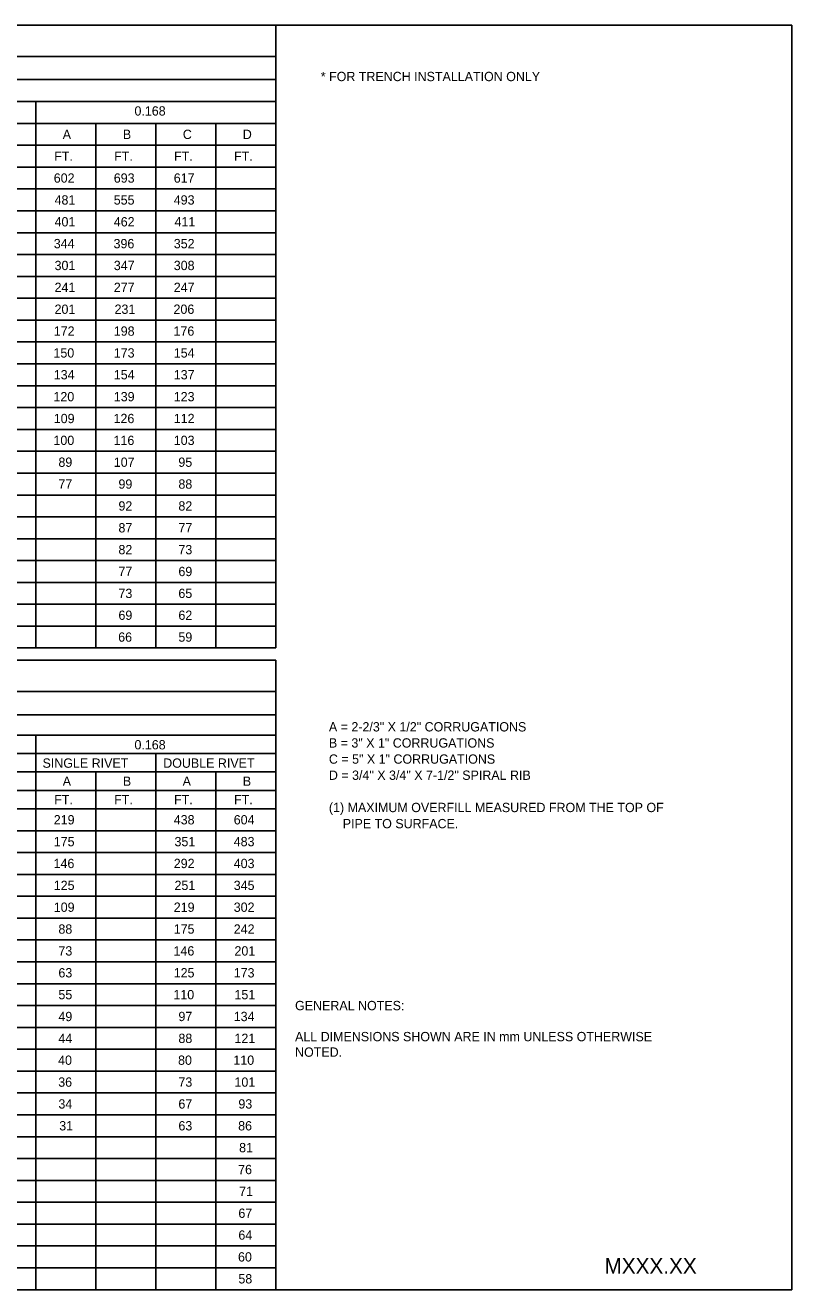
# Model space of a CAD drawing. Extents: x -439.1 to -407.9, y -458.1 to -436.2.
# Drawn here: x -420.2 to -407.86, y -458.05 to -437.68 of the extents above; entities that cross this region are included whole.
import ezdxf

# ---------------------------------------------------------------- set-up
doc = ezdxf.new("R2010")
doc.units = 0
for name, color, linetype in [('Draft_Named_Boundary', 7, 'Continuous'), ('Level 4', 7, 'Continuous'), ('Level 45', 7, 'Continuous'), ('Level 46', 7, 'Continuous')]:
    doc.layers.add(name, color=color, linetype=linetype)

msp = doc.modelspace()

# ---------------------------------------------------------------- linework, layer by layer
at = {"layer": 'Draft_Named_Boundary'}
msp.add_lwpolyline([(-439.109, -458.051), (-407.859, -458.051), (-407.859, -437.676), (-439.109, -437.676)], close=True, dxfattribs=at)
at = {"layer": 'Level 4'}
for p, q in [((-439.109, -437.676), (-416.17, -437.676)), ((-416.17, -447.71), (-416.17, -437.676)), ((-439.109, -438.177), (-416.17, -438.177)), ((-439.109, -438.552), (-416.17, -438.552)), ((-435.493, -438.905), (-416.17, -438.905)), ((-420.035, -447.71), (-420.035, -438.905)), ((-435.493, -439.257), (-416.17, -439.257)), ((-419.069, -447.71), (-419.069, -439.257)), ((-418.103, -447.71), (-418.103, -439.257)), ((-417.136, -447.71), (-417.136, -439.257)), ((-439.109, -439.609), (-416.17, -439.609)), ((-439.109, -439.961), (-416.17, -439.961)), ((-439.109, -440.313), (-416.17, -440.313)), ((-439.109, -440.666), (-416.17, -440.666)), ((-439.109, -441.018), (-416.17, -441.018)), ((-439.109, -441.37), (-416.17, -441.37)), ((-439.109, -441.722), (-416.17, -441.722)), ((-439.109, -442.075), (-416.17, -442.075)), ((-439.109, -442.427), (-416.17, -442.427)), ((-439.109, -442.779), (-416.17, -442.779)), ((-439.109, -443.131), (-416.17, -443.131)), ((-439.109, -443.483), (-416.17, -443.483)), ((-439.109, -443.836), (-416.17, -443.836)), ((-439.109, -444.188), (-416.17, -444.188)), ((-439.109, -444.54), (-416.17, -444.54)), ((-439.109, -444.892), (-416.17, -444.892)), ((-439.109, -445.245), (-416.17, -445.245)), ((-439.109, -445.597), (-416.17, -445.597)), ((-439.109, -445.949), (-416.17, -445.949)), ((-439.109, -446.301), (-416.17, -446.301)), ((-439.109, -446.654), (-416.17, -446.654)), ((-439.109, -447.006), (-416.17, -447.006)), ((-439.109, -447.358), (-416.17, -447.358)), ((-439.109, -447.71), (-416.17, -447.71)), ((-439.109, -447.908), (-416.17, -447.908)), ((-416.17, -458.051), (-416.17, -447.908)), ((-439.109, -448.409), (-416.17, -448.409)), ((-439.109, -448.785), (-416.17, -448.785)), ((-435.493, -449.113), (-416.17, -449.113)), ((-420.035, -458.051), (-420.035, -449.113)), ((-435.493, -449.411), (-416.17, -449.411)), ((-418.103, -458.051), (-418.103, -449.411)), ((-435.493, -449.708), (-416.17, -449.708)), ((-419.069, -458.051), (-419.069, -449.708)), ((-417.136, -458.051), (-417.136, -449.708)), ((-439.109, -450.005), (-416.17, -450.005)), ((-439.109, -450.302), (-416.17, -450.302)), ((-439.109, -450.654), (-416.17, -450.654)), ((-439.109, -451.006), (-416.17, -451.006)), ((-439.109, -451.359), (-416.17, -451.359)), ((-439.109, -451.711), (-416.17, -451.711)), ((-439.109, -452.063), (-416.17, -452.063)), ((-439.109, -452.415), (-416.17, -452.415)), ((-439.109, -452.767), (-416.17, -452.767)), ((-439.109, -453.12), (-416.17, -453.12)), ((-439.109, -453.472), (-416.17, -453.472)), ((-439.109, -453.824), (-416.17, -453.824)), ((-439.109, -454.176), (-416.17, -454.176)), ((-439.109, -454.529), (-416.17, -454.529)), ((-439.109, -454.881), (-416.17, -454.881)), ((-439.109, -455.233), (-416.17, -455.233)), ((-439.109, -455.585), (-416.17, -455.585)), ((-439.109, -455.937), (-416.17, -455.937)), ((-439.109, -456.29), (-416.17, -456.29)), ((-439.109, -456.642), (-416.17, -456.642)), ((-439.109, -456.994), (-416.17, -456.994)), ((-439.109, -457.346), (-416.17, -457.346)), ((-439.109, -457.699), (-416.17, -457.699)), ((-439.109, -458.051), (-416.17, -458.051))]:
    msp.add_line(p, q, dxfattribs=at)

# ---------------------------------------------------------------- texts
for s, p in [('* FOR TRENCH INSTALLATION ONLY', (-415.445, -438.576)), ('0.168', (-418.446, -439.131)), ('A', (-419.602, -439.508)), ('B', (-418.633, -439.508)), ('C', (-417.667, -439.508)), ('D', (-416.701, -439.508)), ('FT.', (-419.739, -439.86)), ('FT.', (-418.773, -439.86)), ('FT.', (-417.807, -439.86)), ('FT.', (-416.841, -439.86)), ('602', (-419.746, -440.212)), ('693', (-418.779, -440.212)), ('617', (-417.813, -440.212)), ('481', (-419.733, -440.565)), ('555', (-418.78, -440.565)), ('493', (-417.813, -440.565)), ('401', (-419.733, -440.917)), ('462', (-418.779, -440.917)), ('411', (-417.801, -440.917)), ('344', (-419.746, -441.269)), ('396', (-418.783, -441.269)), ('352', (-417.813, -441.269)), ('301', (-419.733, -441.621)), ('347', (-418.779, -441.621)), ('308', (-417.813, -441.621)), ('241', (-419.733, -441.973)), ('277', (-418.779, -441.973)), ('247', (-417.813, -441.973)), ('201', (-419.733, -442.326)), ('231', (-418.767, -442.326)), ('206', (-417.817, -442.326)), ('172', (-419.746, -442.678)), ('198', (-418.779, -442.678)), ('176', (-417.817, -442.678)), ('150', (-419.751, -443.03)), ('173', (-418.779, -443.03)), ('154', (-417.813, -443.03)), ('134', (-419.746, -443.382)), ('154', (-418.779, -443.382)), ('137', (-417.813, -443.382)), ('120', (-419.751, -443.735)), ('139', (-418.779, -443.735)), ('123', (-417.813, -443.735)), ('109', (-419.746, -444.087)), ('126', (-418.783, -444.087)), ('112', (-417.813, -444.087)), ('100', (-419.751, -444.439)), ('116', (-418.783, -444.439)), ('103', (-417.813, -444.439)), ('89', (-419.671, -444.791)), ('107', (-418.779, -444.791)), ('95', (-417.739, -444.791)), ('77', (-419.671, -445.143)), ('99', (-418.704, -445.143)), ('88', (-417.738, -445.143)), ('92', (-418.704, -445.496)), ('82', (-417.738, -445.496)), ('87', (-418.704, -445.848)), ('77', (-417.738, -445.848)), ('82', (-418.704, -446.2)), ('73', (-417.738, -446.2)), ('77', (-418.704, -446.552)), ('69', (-417.738, -446.552)), ('73', (-418.704, -446.905)), ('65', (-417.739, -446.905)), ('69', (-418.704, -447.257)), ('62', (-417.738, -447.257)), ('66', (-418.708, -447.609)), ('59', (-417.738, -447.609)), ('0.168', (-418.446, -449.344)), ('SINGLE RIVET', (-419.927, -449.64)), ('DOUBLE RIVET', (-417.983, -449.64)), ('A', (-419.602, -449.931)), ('B', (-418.633, -449.931)), ('A', (-417.67, -449.931)), ('B', (-416.701, -449.931)), ('FT.', (-419.739, -450.228)), ('FT.', (-418.773, -450.228)), ('FT.', (-417.807, -450.228)), ('FT.', (-416.841, -450.228)), ('219', (-419.746, -450.553)), ('438', (-417.813, -450.553)), ('604', (-416.847, -450.553)), ('175', (-419.746, -450.905)), ('351', (-417.801, -450.905)), ('483', (-416.847, -450.905)), ('146', (-419.749, -451.257)), ('292', (-417.813, -451.257)), ('403', (-416.847, -451.257)), ('125', (-419.746, -451.61)), ('251', (-417.801, -451.61)), ('345', (-416.847, -451.61)), ('109', (-419.746, -451.962)), ('219', (-417.813, -451.962)), ('302', (-416.847, -451.962)), ('88', (-419.671, -452.314)), ('175', (-417.814, -452.314)), ('242', (-416.847, -452.314)), ('73', (-419.671, -452.666)), ('146', (-417.817, -452.666)), ('201', (-416.835, -452.666)), ('63', (-419.671, -453.019)), ('125', (-417.814, -453.019)), ('173', (-416.847, -453.019)), ('55', (-419.671, -453.371)), ('110', (-417.819, -453.371)), ('151', (-416.835, -453.371)), ('49', (-419.671, -453.723)), ('97', (-417.738, -453.723)), ('134', (-416.847, -453.723)), ('44', (-419.671, -454.075)), ('88', (-417.738, -454.075)), ('121', (-416.835, -454.075)), ('40', (-419.676, -454.427)), ('80', (-417.744, -454.427)), ('110', (-416.853, -454.427)), ('36', (-419.674, -454.78)), ('73', (-417.738, -454.78)), ('101', (-416.835, -454.78)), ('34', (-419.671, -455.132)), ('67', (-417.738, -455.132)), ('93', (-416.772, -455.132)), ('31', (-419.658, -455.484)), ('63', (-417.738, -455.484)), ('86', (-416.776, -455.484)), ('81', (-416.76, -455.836)), ('76', (-416.776, -456.189)), ('71', (-416.76, -456.541)), ('67', (-416.772, -456.893)), ('64', (-416.772, -457.245)), ('60', (-416.778, -457.597)), ('58', (-416.772, -457.95))]:
    msp.add_text(s, height=0.15, dxfattribs=at).set_placement(p)
at = {"layer": 'Level 45'}
for s, p in [('A = 2-2/3" X 1/2" CORRUGATIONS', (-415.314, -449.055)), ('B = 3" X 1" CORRUGATIONS', (-415.314, -449.315)), ('C = 5" X 1" CORRUGATIONS ', (-415.314, -449.575)), ('D = 3/4" X 3/4" X 7-1/2" SPIRAL RIB', (-415.314, -449.835)), ('(1) MAXIMUM OVERFILL MEASURED FROM THE TOP OF ', (-415.314, -450.355)), ('    PIPE TO SURFACE.  ', (-415.314, -450.615))]:
    msp.add_text(s, height=0.15, dxfattribs=at).set_placement(p)
at = {"layer": 'Level 46'}
for s, height, p in [('GENERAL NOTES:', 0.15, (-415.859, -453.547)), ('ALL DIMENSIONS SHOWN ARE IN mm UNLESS OTHERWISE ', 0.15, (-415.859, -454.047)), ('NOTED.', 0.15, (-415.859, -454.297)), ('MXXX.XX', 0.25, (-410.875, -457.792))]:
    msp.add_text(s, height=height, dxfattribs=at).set_placement(p)

doc.saveas('drawing.dxf')
